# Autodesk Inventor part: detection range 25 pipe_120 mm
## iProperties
Shininess: 20.0
Length Units: 11269
Angle Units: 11279
Time Units: 11290
Mass Units: 11283
Length Display Precision: 3
Angle Display Precision: 2
Part Number: detection range 25 pipe_120 mm
Material: Lexan (klar)
Document SubType Name: Modellieren
Description: Schallfeld 0,25 m
Checked By: Alves
Created: 2005-08
Designer: Klein
Manufacturer: Standard
Standards Organization: Custom
Density: 0.0
Volumn: 0.0
Area: 0.0
PropertySet Name: Model Information
Control State: 0
Master: False
Checked Out: False
BESTELLNUMMER: 0,25 m
ME: ST
Title: Schallfelder
Author: Klein
Comments: keine Bemerkung
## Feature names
1. Innenglocke [Revolution]
2. Umdrehung5 [Revolution]
